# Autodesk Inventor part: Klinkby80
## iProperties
Created: 2010-01
Part Number: Klinkby80
Document SubType Name: Modeling
Designer: TB
Mass: 1088.24 g
Surface Area: 1130.39 cm^2
Volume: 1088.24 cm^3
Density: 1 g/cm^3
Author: TB
